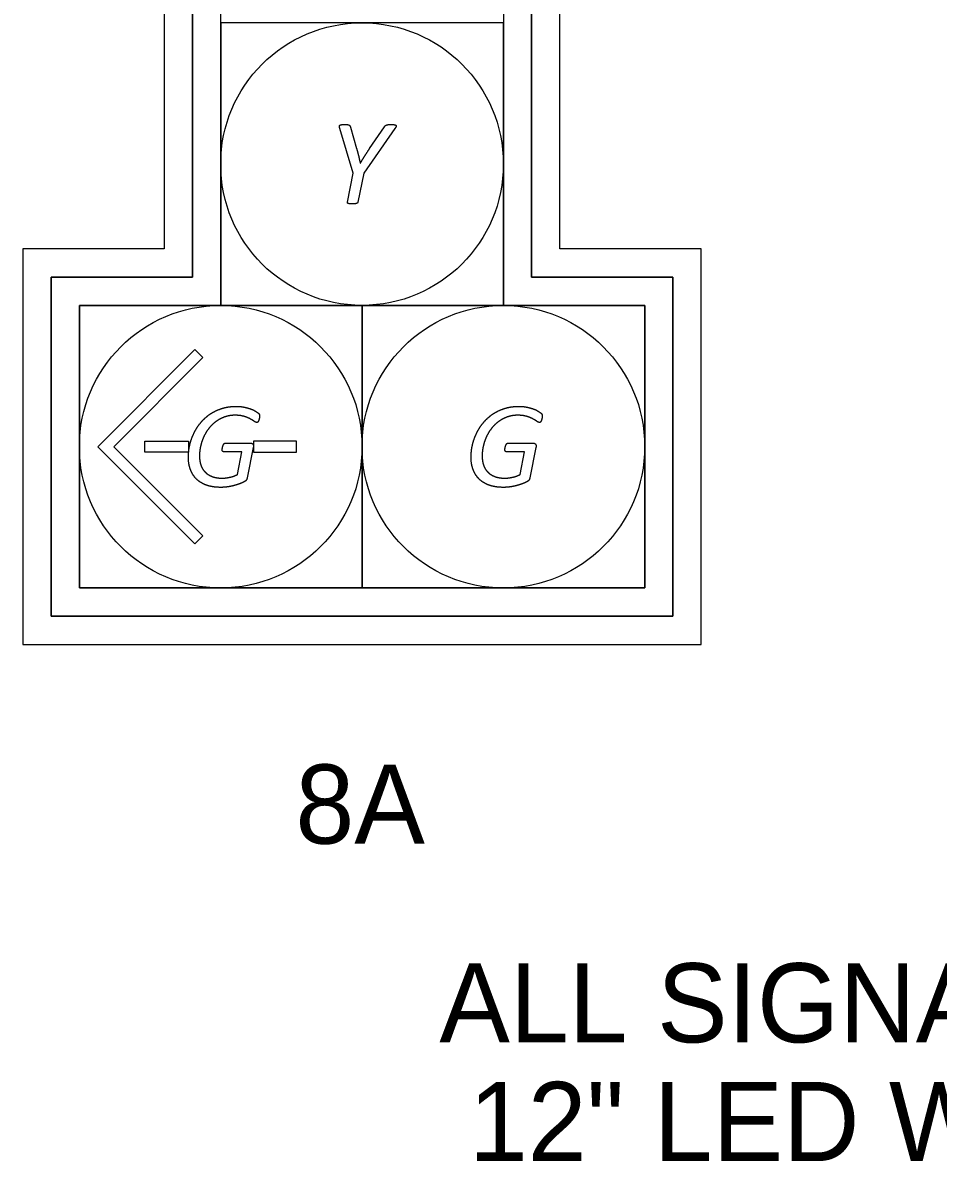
# Model space of a CAD drawing. Extents: x -32.9 to 34, y 0 to 22.3.
# Drawn here: x -15.497 to -13.878, y 17.717 to 19.733 of the extents above; entities that cross this region are included whole.
import ezdxf

# ---------------------------------------------------------------- set-up
doc = ezdxf.new("R2010")
doc.units = 0
doc.layers.add('PF_X_Ground_Line', color=7, linetype='Continuous')
doc.layers.add('PV_P_Saw_Cut_Line', color=7, linetype='Continuous')

msp = doc.modelspace()

# ---------------------------------------------------------------- linework, layer by layer
at = {"layer": 'PV_P_Saw_Cut_Line'}
for p, q in [((-14.918, 19.5486), (-14.9069, 19.5104)), ((-14.918, 19.5486), (-14.9069, 19.5104)), ((-14.8841, 19.5103), (-14.8577, 19.5491)), ((-14.8841, 19.5103), (-14.8577, 19.5491)), ((-14.9006, 19.4846), (-14.9003, 19.4846)), ((-14.9006, 19.4846), (-14.9003, 19.4846)), ((-15.3647, 18.983), (-15.193, 19.1547)), ((-15.193, 19.1547), (-15.1788, 19.1406)), ((-15.1788, 19.1406), (-15.3364, 18.983)), ((-15.193, 18.8113), (-15.3647, 18.983)), ((-15.3364, 18.983), (-15.1788, 18.8254)), ((-15.139, 18.9893), (-15.0947, 18.9893)), ((-15.139, 18.9893), (-15.0947, 18.9893)), ((-15.0897, 18.9817), (-15.1005, 18.9281)), ((-15.0897, 18.9817), (-15.1005, 18.9281)), ((-14.639, 18.9893), (-14.5947, 18.9893)), ((-14.639, 18.9893), (-14.5947, 18.9893)), ((-14.5897, 18.9817), (-14.6005, 18.9281)), ((-14.5897, 18.9817), (-14.6005, 18.9281)), ((-15.1788, 18.8254), (-15.193, 18.8113))]:
    msp.add_line(p, q, dxfattribs=at)
for points in [[(-14.2974, 18.633), (-14.2974, 19.333), (-14.5474, 19.333), (-14.5474, 20.333), (-15.2474, 20.333), (-15.2474, 19.333), (-15.4974, 19.333), (-15.4974, 18.633)], [(-15.4474, 18.683), (-15.4474, 19.283), (-15.1974, 19.283), (-15.1974, 20.283), (-14.5974, 20.283), (-14.5974, 19.283), (-14.3474, 19.283), (-14.3474, 18.683)], [(-14.3474, 18.683), (-14.3474, 19.283), (-14.5974, 19.283), (-14.5974, 20.283), (-15.1974, 20.283), (-15.1974, 19.283), (-15.4474, 19.283), (-15.4474, 18.683)], [(-15.3974, 18.733), (-15.3974, 19.233), (-15.1474, 19.233), (-15.1474, 20.233), (-14.6474, 20.233), (-14.6474, 19.233), (-14.3974, 19.233), (-14.3974, 18.733)], [(-15.1474, 19.233), (-14.6474, 19.233), (-14.6474, 19.733), (-15.1474, 19.733)], [(-15.3974, 19.233), (-15.3974, 18.733), (-14.8974, 18.733), (-14.8974, 19.233)], [(-14.8974, 18.733), (-14.3974, 18.733), (-14.3974, 19.233), (-14.8974, 19.233)], [(-15.2814, 18.973), (-15.2814, 18.993), (-15.2043, 18.993), (-15.2043, 18.973)], [(-15.0135, 18.973), (-15.0135, 18.993), (-15.0895, 18.993), (-15.0895, 18.973)]]:
    msp.add_lwpolyline(points, close=True, dxfattribs=at)
for points in [[(-14.9233, 19.4157), (-14.9129, 19.4672), (-14.9367, 19.5458)], [(-14.9233, 19.4157), (-14.9129, 19.4672), (-14.9367, 19.5458)], [(-14.8393, 19.5458), (-14.8944, 19.4672), (-14.9046, 19.4157)], [(-14.8393, 19.5458), (-14.8944, 19.4672), (-14.9046, 19.4157)], [(-15.1179, 18.9336), (-15.1098, 18.974), (-15.142, 18.974)], [(-15.1179, 18.9336), (-15.1098, 18.974), (-15.142, 18.974)], [(-14.6179, 18.9336), (-14.6098, 18.974), (-14.642, 18.974)], [(-14.6179, 18.9336), (-14.6098, 18.974), (-14.642, 18.974)]]:
    msp.add_lwpolyline(points, dxfattribs=at)
for centre in [(-14.8974, 19.483), (-15.1474, 18.983), (-14.6474, 18.983)]:
    msp.add_circle(centre, 0.25, dxfattribs=at)
for points in [[(-14.9375, 19.5496), (-14.9377, 19.551), (-14.9368, 19.5517)], [(-14.9375, 19.5496), (-14.9377, 19.551), (-14.9368, 19.5517)], [(-14.9367, 19.5458), (-14.9373, 19.5482), (-14.9375, 19.5496)], [(-14.9367, 19.5458), (-14.9373, 19.5482), (-14.9375, 19.5496)], [(-14.9368, 19.5517), (-14.9359, 19.5525), (-14.9339, 19.5527)], [(-14.9368, 19.5517), (-14.9359, 19.5525), (-14.9339, 19.5527)], [(-14.9339, 19.5527), (-14.932, 19.553), (-14.9282, 19.553)], [(-14.9339, 19.5527), (-14.932, 19.553), (-14.9282, 19.553)], [(-14.9282, 19.553), (-14.9253, 19.553), (-14.9234, 19.5529)], [(-14.9282, 19.553), (-14.9253, 19.553), (-14.9234, 19.5529)], [(-14.9234, 19.5529), (-14.9216, 19.5527), (-14.9205, 19.5522)], [(-14.9234, 19.5529), (-14.9216, 19.5527), (-14.9205, 19.5522)], [(-14.9205, 19.5522), (-14.9194, 19.5516), (-14.9189, 19.5508)], [(-14.9205, 19.5522), (-14.9194, 19.5516), (-14.9189, 19.5508)], [(-14.9189, 19.5508), (-14.9185, 19.55), (-14.918, 19.5486)], [(-14.9189, 19.5508), (-14.9185, 19.55), (-14.918, 19.5486)], [(-14.8577, 19.5491), (-14.857, 19.5502), (-14.8562, 19.551)], [(-14.8577, 19.5491), (-14.857, 19.5502), (-14.8562, 19.551)], [(-14.8562, 19.551), (-14.8554, 19.5517), (-14.8541, 19.5522)], [(-14.8562, 19.551), (-14.8554, 19.5517), (-14.8541, 19.5522)], [(-14.8541, 19.5522), (-14.8529, 19.5527), (-14.8509, 19.5529)], [(-14.8541, 19.5522), (-14.8529, 19.5527), (-14.8509, 19.5529)], [(-14.8509, 19.5529), (-14.849, 19.553), (-14.8458, 19.553)], [(-14.8509, 19.5529), (-14.849, 19.553), (-14.8458, 19.553)], [(-14.8458, 19.553), (-14.8419, 19.553), (-14.8398, 19.5526)], [(-14.8458, 19.553), (-14.8419, 19.553), (-14.8398, 19.5526)], [(-14.8398, 19.5526), (-14.8378, 19.5523), (-14.8372, 19.5514)], [(-14.8398, 19.5526), (-14.8378, 19.5523), (-14.8372, 19.5514)], [(-14.8372, 19.5491), (-14.8379, 19.5477), (-14.8393, 19.5458)], [(-14.8372, 19.5491), (-14.8379, 19.5477), (-14.8393, 19.5458)], [(-14.8372, 19.5514), (-14.8366, 19.5505), (-14.8372, 19.5491)], [(-14.8372, 19.5514), (-14.8366, 19.5505), (-14.8372, 19.5491)], [(-14.9069, 19.5104), (-14.905, 19.5037), (-14.9035, 19.4975)], [(-14.9069, 19.5104), (-14.905, 19.5037), (-14.9035, 19.4975)], [(-14.9035, 19.4975), (-14.902, 19.4913), (-14.9006, 19.4846)], [(-14.9035, 19.4975), (-14.902, 19.4913), (-14.9006, 19.4846)], [(-14.9003, 19.4846), (-14.8965, 19.4911), (-14.8925, 19.4974)], [(-14.9003, 19.4846), (-14.8965, 19.4911), (-14.8925, 19.4974)], [(-14.8925, 19.4974), (-14.8885, 19.5038), (-14.8841, 19.5103)], [(-14.8925, 19.4974), (-14.8885, 19.5038), (-14.8841, 19.5103)], [(-14.9231, 19.4143), (-14.9234, 19.4149), (-14.9233, 19.4157)], [(-14.9231, 19.4143), (-14.9234, 19.4149), (-14.9233, 19.4157)], [(-14.9046, 19.4157), (-14.9049, 19.4149), (-14.9055, 19.4143)], [(-14.9046, 19.4157), (-14.9049, 19.4149), (-14.9055, 19.4143)], [(-14.9218, 19.4133), (-14.9227, 19.4136), (-14.9231, 19.4143)], [(-14.9218, 19.4133), (-14.9227, 19.4136), (-14.9231, 19.4143)], [(-14.9191, 19.4126), (-14.9208, 19.4129), (-14.9218, 19.4133)], [(-14.9191, 19.4126), (-14.9208, 19.4129), (-14.9218, 19.4133)], [(-14.9147, 19.4124), (-14.9174, 19.4124), (-14.9191, 19.4126)], [(-14.9147, 19.4124), (-14.9174, 19.4124), (-14.9191, 19.4126)], [(-14.9103, 19.4126), (-14.9121, 19.4124), (-14.9147, 19.4124)], [(-14.9103, 19.4126), (-14.9121, 19.4124), (-14.9147, 19.4124)], [(-14.9072, 19.4133), (-14.9084, 19.4129), (-14.9103, 19.4126)], [(-14.9072, 19.4133), (-14.9084, 19.4129), (-14.9103, 19.4126)], [(-14.9055, 19.4143), (-14.9061, 19.4136), (-14.9072, 19.4133)], [(-14.9055, 19.4143), (-14.9061, 19.4136), (-14.9072, 19.4133)], [(-15.1446, 19.0508), (-15.1333, 19.0543), (-15.1201, 19.0543)], [(-15.1446, 19.0508), (-15.1333, 19.0543), (-15.1201, 19.0543)], [(-15.1201, 19.0543), (-15.1126, 19.0543), (-15.106, 19.053)], [(-15.1201, 19.0543), (-15.1126, 19.0543), (-15.106, 19.053)], [(-15.106, 19.053), (-15.0995, 19.0516), (-15.0943, 19.0498)], [(-15.106, 19.053), (-15.0995, 19.0516), (-15.0943, 19.0498)], [(-14.6446, 19.0508), (-14.6333, 19.0543), (-14.6201, 19.0543)], [(-14.6446, 19.0508), (-14.6333, 19.0543), (-14.6201, 19.0543)], [(-14.6201, 19.0543), (-14.6126, 19.0543), (-14.606, 19.053)], [(-14.6201, 19.0543), (-14.6126, 19.0543), (-14.606, 19.053)], [(-14.606, 19.053), (-14.5995, 19.0516), (-14.5943, 19.0498)], [(-14.606, 19.053), (-14.5995, 19.0516), (-14.5943, 19.0498)], [(-15.182, 19.0264), (-15.1748, 19.0349), (-15.1653, 19.0411)], [(-15.182, 19.0264), (-15.1748, 19.0349), (-15.1653, 19.0411)], [(-15.1653, 19.0411), (-15.1559, 19.0472), (-15.1446, 19.0508)], [(-15.1653, 19.0411), (-15.1559, 19.0472), (-15.1446, 19.0508)], [(-15.1399, 19.0357), (-15.1483, 19.0328), (-15.1553, 19.0278)], [(-15.1399, 19.0357), (-15.1483, 19.0328), (-15.1553, 19.0278)], [(-15.122, 19.0386), (-15.1316, 19.0386), (-15.1399, 19.0357)], [(-15.122, 19.0386), (-15.1316, 19.0386), (-15.1399, 19.0357)], [(-15.1062, 19.0366), (-15.1128, 19.0386), (-15.122, 19.0386)], [(-15.1062, 19.0366), (-15.1128, 19.0386), (-15.122, 19.0386)], [(-15.0951, 19.0321), (-15.0997, 19.0346), (-15.1062, 19.0366)], [(-15.0951, 19.0321), (-15.0997, 19.0346), (-15.1062, 19.0366)], [(-15.0878, 19.0277), (-15.0905, 19.0297), (-15.0951, 19.0321)], [(-15.0878, 19.0277), (-15.0905, 19.0297), (-15.0951, 19.0321)], [(-15.0943, 19.0498), (-15.0891, 19.0479), (-15.0856, 19.0456)], [(-15.0943, 19.0498), (-15.0891, 19.0479), (-15.0856, 19.0456)], [(-15.0856, 19.0456), (-15.082, 19.0434), (-15.0807, 19.0422)], [(-15.0856, 19.0456), (-15.082, 19.0434), (-15.0807, 19.0422)], [(-15.0807, 19.0422), (-15.0794, 19.041), (-15.079, 19.0399)], [(-15.0807, 19.0422), (-15.0794, 19.041), (-15.079, 19.0399)], [(-15.0792, 19.033), (-15.0794, 19.0317), (-15.0799, 19.0304)], [(-15.0792, 19.033), (-15.0794, 19.0317), (-15.0799, 19.0304)], [(-15.0787, 19.0353), (-15.0789, 19.0342), (-15.0792, 19.033)], [(-15.0787, 19.0353), (-15.0789, 19.0342), (-15.0792, 19.033)], [(-15.079, 19.0399), (-15.0786, 19.0389), (-15.0786, 19.0372)], [(-15.079, 19.0399), (-15.0786, 19.0389), (-15.0786, 19.0372)], [(-15.0786, 19.0372), (-15.0786, 19.0365), (-15.0787, 19.0353)], [(-15.0786, 19.0372), (-15.0786, 19.0365), (-15.0787, 19.0353)], [(-14.682, 19.0264), (-14.6748, 19.0349), (-14.6653, 19.0411)], [(-14.682, 19.0264), (-14.6748, 19.0349), (-14.6653, 19.0411)], [(-14.6653, 19.0411), (-14.6559, 19.0472), (-14.6446, 19.0508)], [(-14.6653, 19.0411), (-14.6559, 19.0472), (-14.6446, 19.0508)], [(-14.6399, 19.0357), (-14.6483, 19.0328), (-14.6553, 19.0278)], [(-14.6399, 19.0357), (-14.6483, 19.0328), (-14.6553, 19.0278)], [(-14.622, 19.0386), (-14.6316, 19.0386), (-14.6399, 19.0357)], [(-14.622, 19.0386), (-14.6316, 19.0386), (-14.6399, 19.0357)], [(-14.6062, 19.0366), (-14.6128, 19.0386), (-14.622, 19.0386)], [(-14.6062, 19.0366), (-14.6128, 19.0386), (-14.622, 19.0386)], [(-14.5951, 19.0321), (-14.5997, 19.0346), (-14.6062, 19.0366)], [(-14.5951, 19.0321), (-14.5997, 19.0346), (-14.6062, 19.0366)], [(-14.5878, 19.0277), (-14.5905, 19.0297), (-14.5951, 19.0321)], [(-14.5878, 19.0277), (-14.5905, 19.0297), (-14.5951, 19.0321)], [(-14.5943, 19.0498), (-14.5891, 19.0479), (-14.5856, 19.0456)], [(-14.5943, 19.0498), (-14.5891, 19.0479), (-14.5856, 19.0456)], [(-14.5856, 19.0456), (-14.582, 19.0434), (-14.5807, 19.0422)], [(-14.5856, 19.0456), (-14.582, 19.0434), (-14.5807, 19.0422)], [(-14.5807, 19.0422), (-14.5794, 19.041), (-14.579, 19.0399)], [(-14.5807, 19.0422), (-14.5794, 19.041), (-14.579, 19.0399)], [(-14.5792, 19.033), (-14.5794, 19.0317), (-14.5799, 19.0304)], [(-14.5792, 19.033), (-14.5794, 19.0317), (-14.5799, 19.0304)], [(-14.5787, 19.0353), (-14.5789, 19.0342), (-14.5792, 19.033)], [(-14.5787, 19.0353), (-14.5789, 19.0342), (-14.5792, 19.033)], [(-14.579, 19.0399), (-14.5786, 19.0389), (-14.5786, 19.0372)], [(-14.579, 19.0399), (-14.5786, 19.0389), (-14.5786, 19.0372)], [(-14.5786, 19.0372), (-14.5786, 19.0365), (-14.5787, 19.0353)], [(-14.5786, 19.0372), (-14.5786, 19.0365), (-14.5787, 19.0353)], [(-15.1943, 19.0079), (-15.1893, 19.0179), (-15.182, 19.0264)], [(-15.1943, 19.0079), (-15.1893, 19.0179), (-15.182, 19.0264)], [(-15.1678, 19.016), (-15.1733, 19.0091), (-15.1771, 19.0011)], [(-15.1678, 19.016), (-15.1733, 19.0091), (-15.1771, 19.0011)], [(-15.1553, 19.0278), (-15.1623, 19.0228), (-15.1678, 19.016)], [(-15.1553, 19.0278), (-15.1623, 19.0228), (-15.1678, 19.016)], [(-15.0834, 19.0258), (-15.085, 19.0258), (-15.0878, 19.0277)], [(-15.0834, 19.0258), (-15.085, 19.0258), (-15.0878, 19.0277)], [(-15.082, 19.0264), (-15.0827, 19.0258), (-15.0834, 19.0258)], [(-15.082, 19.0264), (-15.0827, 19.0258), (-15.0834, 19.0258)], [(-15.0808, 19.028), (-15.0814, 19.027), (-15.082, 19.0264)], [(-15.0808, 19.028), (-15.0814, 19.027), (-15.082, 19.0264)], [(-15.0799, 19.0304), (-15.0803, 19.029), (-15.0808, 19.028)], [(-15.0799, 19.0304), (-15.0803, 19.029), (-15.0808, 19.028)], [(-14.6943, 19.0079), (-14.6893, 19.0179), (-14.682, 19.0264)], [(-14.6943, 19.0079), (-14.6893, 19.0179), (-14.682, 19.0264)], [(-14.6678, 19.016), (-14.6733, 19.0091), (-14.6771, 19.0011)], [(-14.6678, 19.016), (-14.6733, 19.0091), (-14.6771, 19.0011)], [(-14.6553, 19.0278), (-14.6623, 19.0228), (-14.6678, 19.016)], [(-14.6553, 19.0278), (-14.6623, 19.0228), (-14.6678, 19.016)], [(-14.5834, 19.0258), (-14.585, 19.0258), (-14.5878, 19.0277)], [(-14.5834, 19.0258), (-14.585, 19.0258), (-14.5878, 19.0277)], [(-14.582, 19.0264), (-14.5827, 19.0258), (-14.5834, 19.0258)], [(-14.582, 19.0264), (-14.5827, 19.0258), (-14.5834, 19.0258)], [(-14.5808, 19.028), (-14.5814, 19.027), (-14.582, 19.0264)], [(-14.5808, 19.028), (-14.5814, 19.027), (-14.582, 19.0264)], [(-14.5799, 19.0304), (-14.5803, 19.029), (-14.5808, 19.028)], [(-14.5799, 19.0304), (-14.5803, 19.029), (-14.5808, 19.028)], [(-15.2019, 18.9867), (-15.1992, 18.9979), (-15.1943, 19.0079)], [(-15.2019, 18.9867), (-15.1992, 18.9979), (-15.1943, 19.0079)], [(-15.1771, 19.0011), (-15.1809, 18.9931), (-15.1829, 18.9842)], [(-15.1771, 19.0011), (-15.1809, 18.9931), (-15.1829, 18.9842)], [(-14.7019, 18.9867), (-14.6992, 18.9979), (-14.6943, 19.0079)], [(-14.7019, 18.9867), (-14.6992, 18.9979), (-14.6943, 19.0079)], [(-14.6771, 19.0011), (-14.6809, 18.9931), (-14.6829, 18.9842)], [(-14.6771, 19.0011), (-14.6809, 18.9931), (-14.6829, 18.9842)], [(-15.2045, 18.964), (-15.2045, 18.9756), (-15.2019, 18.9867)], [(-15.2045, 18.964), (-15.2045, 18.9756), (-15.2019, 18.9867)], [(-15.1829, 18.9842), (-15.1849, 18.9754), (-15.1849, 18.9664)], [(-15.1829, 18.9842), (-15.1849, 18.9754), (-15.1849, 18.9664)], [(-15.1447, 18.9776), (-15.1447, 18.9783), (-15.1445, 18.9796)], [(-15.1447, 18.9776), (-15.1447, 18.9783), (-15.1445, 18.9796)], [(-15.144, 18.9749), (-15.1447, 18.9758), (-15.1447, 18.9776)], [(-15.144, 18.9749), (-15.1447, 18.9758), (-15.1447, 18.9776)], [(-15.1445, 18.9796), (-15.1444, 18.9808), (-15.1441, 18.9821)], [(-15.1445, 18.9796), (-15.1444, 18.9808), (-15.1441, 18.9821)], [(-15.1441, 18.9821), (-15.1438, 18.9834), (-15.1433, 18.9847)], [(-15.1441, 18.9821), (-15.1438, 18.9834), (-15.1433, 18.9847)], [(-15.142, 18.974), (-15.1433, 18.974), (-15.144, 18.9749)], [(-15.142, 18.974), (-15.1433, 18.974), (-15.144, 18.9749)], [(-15.1433, 18.9847), (-15.1429, 18.986), (-15.1422, 18.987)], [(-15.1433, 18.9847), (-15.1429, 18.986), (-15.1422, 18.987)], [(-15.1422, 18.987), (-15.1416, 18.9881), (-15.1408, 18.9887)], [(-15.1422, 18.987), (-15.1416, 18.9881), (-15.1408, 18.9887)], [(-15.1408, 18.9887), (-15.14, 18.9893), (-15.139, 18.9893)], [(-15.1408, 18.9887), (-15.14, 18.9893), (-15.139, 18.9893)], [(-15.0947, 18.9893), (-15.0917, 18.9893), (-15.0904, 18.9872)], [(-15.0947, 18.9893), (-15.0917, 18.9893), (-15.0904, 18.9872)], [(-15.0904, 18.9872), (-15.089, 18.9852), (-15.0897, 18.9817)], [(-15.0904, 18.9872), (-15.089, 18.9852), (-15.0897, 18.9817)], [(-14.7045, 18.964), (-14.7045, 18.9756), (-14.7019, 18.9867)], [(-14.7045, 18.964), (-14.7045, 18.9756), (-14.7019, 18.9867)], [(-14.6829, 18.9842), (-14.6849, 18.9754), (-14.6849, 18.9664)], [(-14.6829, 18.9842), (-14.6849, 18.9754), (-14.6849, 18.9664)], [(-14.6447, 18.9776), (-14.6447, 18.9783), (-14.6445, 18.9796)], [(-14.6447, 18.9776), (-14.6447, 18.9783), (-14.6445, 18.9796)], [(-14.644, 18.9749), (-14.6447, 18.9758), (-14.6447, 18.9776)], [(-14.644, 18.9749), (-14.6447, 18.9758), (-14.6447, 18.9776)], [(-14.6445, 18.9796), (-14.6444, 18.9808), (-14.6441, 18.9821)], [(-14.6445, 18.9796), (-14.6444, 18.9808), (-14.6441, 18.9821)], [(-14.6441, 18.9821), (-14.6438, 18.9834), (-14.6433, 18.9847)], [(-14.6441, 18.9821), (-14.6438, 18.9834), (-14.6433, 18.9847)], [(-14.642, 18.974), (-14.6433, 18.974), (-14.644, 18.9749)], [(-14.642, 18.974), (-14.6433, 18.974), (-14.644, 18.9749)], [(-14.6433, 18.9847), (-14.6429, 18.986), (-14.6422, 18.987)], [(-14.6433, 18.9847), (-14.6429, 18.986), (-14.6422, 18.987)], [(-14.6422, 18.987), (-14.6416, 18.9881), (-14.6408, 18.9887)], [(-14.6422, 18.987), (-14.6416, 18.9881), (-14.6408, 18.9887)], [(-14.6408, 18.9887), (-14.64, 18.9893), (-14.639, 18.9893)], [(-14.6408, 18.9887), (-14.64, 18.9893), (-14.639, 18.9893)], [(-14.5947, 18.9893), (-14.5917, 18.9893), (-14.5904, 18.9872)], [(-14.5947, 18.9893), (-14.5917, 18.9893), (-14.5904, 18.9872)], [(-14.5904, 18.9872), (-14.589, 18.9852), (-14.5897, 18.9817)], [(-14.5904, 18.9872), (-14.589, 18.9852), (-14.5897, 18.9817)], [(-15.2007, 18.9419), (-15.2045, 18.9517), (-15.2045, 18.964)], [(-15.2007, 18.9419), (-15.2045, 18.9517), (-15.2045, 18.964)], [(-15.1849, 18.9664), (-15.1849, 18.9569), (-15.1822, 18.9496)], [(-15.1849, 18.9664), (-15.1849, 18.9569), (-15.1822, 18.9496)], [(-14.7007, 18.9419), (-14.7045, 18.9517), (-14.7045, 18.964)], [(-14.7007, 18.9419), (-14.7045, 18.9517), (-14.7045, 18.964)], [(-14.6849, 18.9664), (-14.6849, 18.9569), (-14.6822, 18.9496)], [(-14.6849, 18.9664), (-14.6849, 18.9569), (-14.6822, 18.9496)], [(-15.1897, 18.9252), (-15.197, 18.9321), (-15.2007, 18.9419)], [(-15.1897, 18.9252), (-15.197, 18.9321), (-15.2007, 18.9419)], [(-15.1822, 18.9496), (-15.1794, 18.9423), (-15.1742, 18.9374)], [(-15.1822, 18.9496), (-15.1794, 18.9423), (-15.1742, 18.9374)], [(-15.1742, 18.9374), (-15.1691, 18.9324), (-15.1617, 18.9299)], [(-15.1742, 18.9374), (-15.1691, 18.9324), (-15.1617, 18.9299)], [(-15.1314, 18.9289), (-15.1241, 18.9304), (-15.1179, 18.9336)], [(-15.1314, 18.9289), (-15.1241, 18.9304), (-15.1179, 18.9336)], [(-14.6897, 18.9252), (-14.697, 18.9321), (-14.7007, 18.9419)], [(-14.6897, 18.9252), (-14.697, 18.9321), (-14.7007, 18.9419)], [(-14.6822, 18.9496), (-14.6794, 18.9423), (-14.6742, 18.9374)], [(-14.6822, 18.9496), (-14.6794, 18.9423), (-14.6742, 18.9374)], [(-14.6742, 18.9374), (-14.6691, 18.9324), (-14.6617, 18.9299)], [(-14.6742, 18.9374), (-14.6691, 18.9324), (-14.6617, 18.9299)], [(-14.6314, 18.9289), (-14.6241, 18.9304), (-14.6179, 18.9336)], [(-14.6314, 18.9289), (-14.6241, 18.9304), (-14.6179, 18.9336)], [(-15.1719, 18.9147), (-15.1825, 18.9183), (-15.1897, 18.9252)], [(-15.1719, 18.9147), (-15.1825, 18.9183), (-15.1897, 18.9252)], [(-15.1472, 18.911), (-15.1612, 18.911), (-15.1719, 18.9147)], [(-15.1472, 18.911), (-15.1612, 18.911), (-15.1719, 18.9147)], [(-15.1617, 18.9299), (-15.1544, 18.9273), (-15.1454, 18.9273)], [(-15.1617, 18.9299), (-15.1544, 18.9273), (-15.1454, 18.9273)], [(-15.1315, 18.9125), (-15.139, 18.911), (-15.1472, 18.911)], [(-15.1315, 18.9125), (-15.139, 18.911), (-15.1472, 18.911)], [(-15.1454, 18.9273), (-15.1387, 18.9273), (-15.1314, 18.9289)], [(-15.1454, 18.9273), (-15.1387, 18.9273), (-15.1314, 18.9289)], [(-15.118, 18.9159), (-15.124, 18.9139), (-15.1315, 18.9125)], [(-15.118, 18.9159), (-15.124, 18.9139), (-15.1315, 18.9125)], [(-15.1081, 18.9197), (-15.112, 18.9178), (-15.118, 18.9159)], [(-15.1081, 18.9197), (-15.112, 18.9178), (-15.118, 18.9159)], [(-15.1032, 18.9226), (-15.1042, 18.9216), (-15.1081, 18.9197)], [(-15.1032, 18.9226), (-15.1042, 18.9216), (-15.1081, 18.9197)], [(-15.1016, 18.9248), (-15.1023, 18.9235), (-15.1032, 18.9226)], [(-15.1016, 18.9248), (-15.1023, 18.9235), (-15.1032, 18.9226)], [(-15.1005, 18.9281), (-15.1009, 18.926), (-15.1016, 18.9248)], [(-15.1005, 18.9281), (-15.1009, 18.926), (-15.1016, 18.9248)], [(-14.6719, 18.9147), (-14.6825, 18.9183), (-14.6897, 18.9252)], [(-14.6719, 18.9147), (-14.6825, 18.9183), (-14.6897, 18.9252)], [(-14.6472, 18.911), (-14.6612, 18.911), (-14.6719, 18.9147)], [(-14.6472, 18.911), (-14.6612, 18.911), (-14.6719, 18.9147)], [(-14.6617, 18.9299), (-14.6544, 18.9273), (-14.6454, 18.9273)], [(-14.6617, 18.9299), (-14.6544, 18.9273), (-14.6454, 18.9273)], [(-14.6315, 18.9125), (-14.639, 18.911), (-14.6472, 18.911)], [(-14.6315, 18.9125), (-14.639, 18.911), (-14.6472, 18.911)], [(-14.6454, 18.9273), (-14.6387, 18.9273), (-14.6314, 18.9289)], [(-14.6454, 18.9273), (-14.6387, 18.9273), (-14.6314, 18.9289)], [(-14.618, 18.9159), (-14.624, 18.9139), (-14.6315, 18.9125)], [(-14.618, 18.9159), (-14.624, 18.9139), (-14.6315, 18.9125)], [(-14.6081, 18.9197), (-14.612, 18.9178), (-14.618, 18.9159)], [(-14.6081, 18.9197), (-14.612, 18.9178), (-14.618, 18.9159)], [(-14.6032, 18.9226), (-14.6042, 18.9216), (-14.6081, 18.9197)], [(-14.6032, 18.9226), (-14.6042, 18.9216), (-14.6081, 18.9197)], [(-14.6016, 18.9248), (-14.6023, 18.9235), (-14.6032, 18.9226)], [(-14.6016, 18.9248), (-14.6023, 18.9235), (-14.6032, 18.9226)], [(-14.6005, 18.9281), (-14.6009, 18.926), (-14.6016, 18.9248)], [(-14.6005, 18.9281), (-14.6009, 18.926), (-14.6016, 18.9248)]]:
    msp.add_open_spline(points, degree=2, dxfattribs=at)

# ---------------------------------------------------------------- texts
at = {"layer": 'PF_X_Ground_Line'}
for s, p in [('8A', (-15.0152, 18.2806)), ('ALL SIGNAL HEADS SHALL BE ', (-14.7607, 17.929)), ('12" LED WITH BACKPLATES.', (-14.7083, 17.719))]:
    msp.add_text(s, height=0.14, dxfattribs=at).set_placement(p)

doc.saveas('drawing.dxf')
